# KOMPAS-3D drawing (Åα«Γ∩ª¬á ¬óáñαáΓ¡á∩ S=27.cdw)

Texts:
  Протяжка  квадратная S=27
  Размерные надписи
  Линия выноски #2
  Шероховатость
  № ст.
  № зуба
  Подъём на зуб
  Диаметр
  зубьев
  Допуск
  Угол
  Symbol type A (plotter)
  Поперечный профиль калибрующих зубьев (2:1)
  Поперечный профиль режущих зубьев (2:1)
  отв. центровое В3,15 ГОСТ 14034-84
  с двух сторон
  ГОСТ 5264-81-С3
  Ra 0,8
  Ra 3,2
  Ra 0.8
  Ra 3.2
  Продольный профиль зубьев
  1. Материал рабочей части: сталь P6M5 ГОСТ 19265-73; хвостовой
  части: сталь 40Х ГОСТ 4543-90.
  2. Твердость: режущей части, передней и задней направляющих HRC
  62...65; переднего хвостовика HRC 40...47.
  3. На поверхности протяжки не допускаются трещины, раковины,
  заусенцы, следы коррозии, а на шлифованных поверхностях, кроме
  того черновины и поджоги.
  4. Радиальное биение по всей длине протяжки допускается только
  одностороннее и не должно превышать  0.05 мм.
  5. На зубьях №1-№36 сделать по две, а на зубьях №37-№52 по одной
  стружкоразделительной канавке, расположенных в шахматном порядке.
  6. Неуказанные предельные отклонения: H14, h14,  JT14 2 .
  7. Маркировать: материал режущей части, расстояние между гранями,
  класс точности, товарный знак завода изготовителя.
  8. Остальные технические требования по ГОСТ 16492-70.
  Протяжка
  квадратная S=27
Dimensions and other numbers on the sheet: 1,2,5; 3; 4; 27.060; 27.120; 27.180; 27.240; 27.300; 27.360; 27.420; 27.480; 27.540; 27.600; 27.660; 27.720; 27.780; 27.840; 27.900; 27.960; 28.020; 28.080; 28.140; 28.200; 28.320; 28.420; 28.520; 28.620; 28.720; 28.820; 28.920; 29.020; 29.120; 29.220; 29.320; 29.420; 29.520; 29.620; 29.720; 29.820; 1; 2; 5; 6; 7; 8; 9; 10; 11; 12; 13; 14; 15; 16; 17; 18; 19; 20; 21; 22; 23; 24; 25; 26; 27; 28; 29; 30; 31; 32; 33; 34; 35; 36; 0,030; 0,050; -0,015; 1-36,67-70; 37-52; 53-66; 1.5; 2.0; 4.5; 2.3; 120; 125; 29.980; 30.120; 30.260; 30.400; 30.540; 30.680; 30.820; 30.960; 31.100; 31.240; 31.380; 31.520; 31.660; 31.800; 31.940; 32.080; 32.290; 32.450; 32.610; 32.770; 32.930; 33.090; 33.250; 33.410; 33.570; 33.730; 33.890; 34.050; 34.210; 34.300; 37; 38; 39; 40; 41; 42; 43; 44; 45; 46; 47; 48; 49; 50; 51; 52; 53; 54; 55; 56; 57; 58; 59; 60; 61; 62; 63; 64; 65; 66; 67; 68; 69; 70; 0,070; 0,080; -0,008; 34,300; 185; 905; 2,5; 200; 160; 130; 0,7; 1,5; 2:1; 10,5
